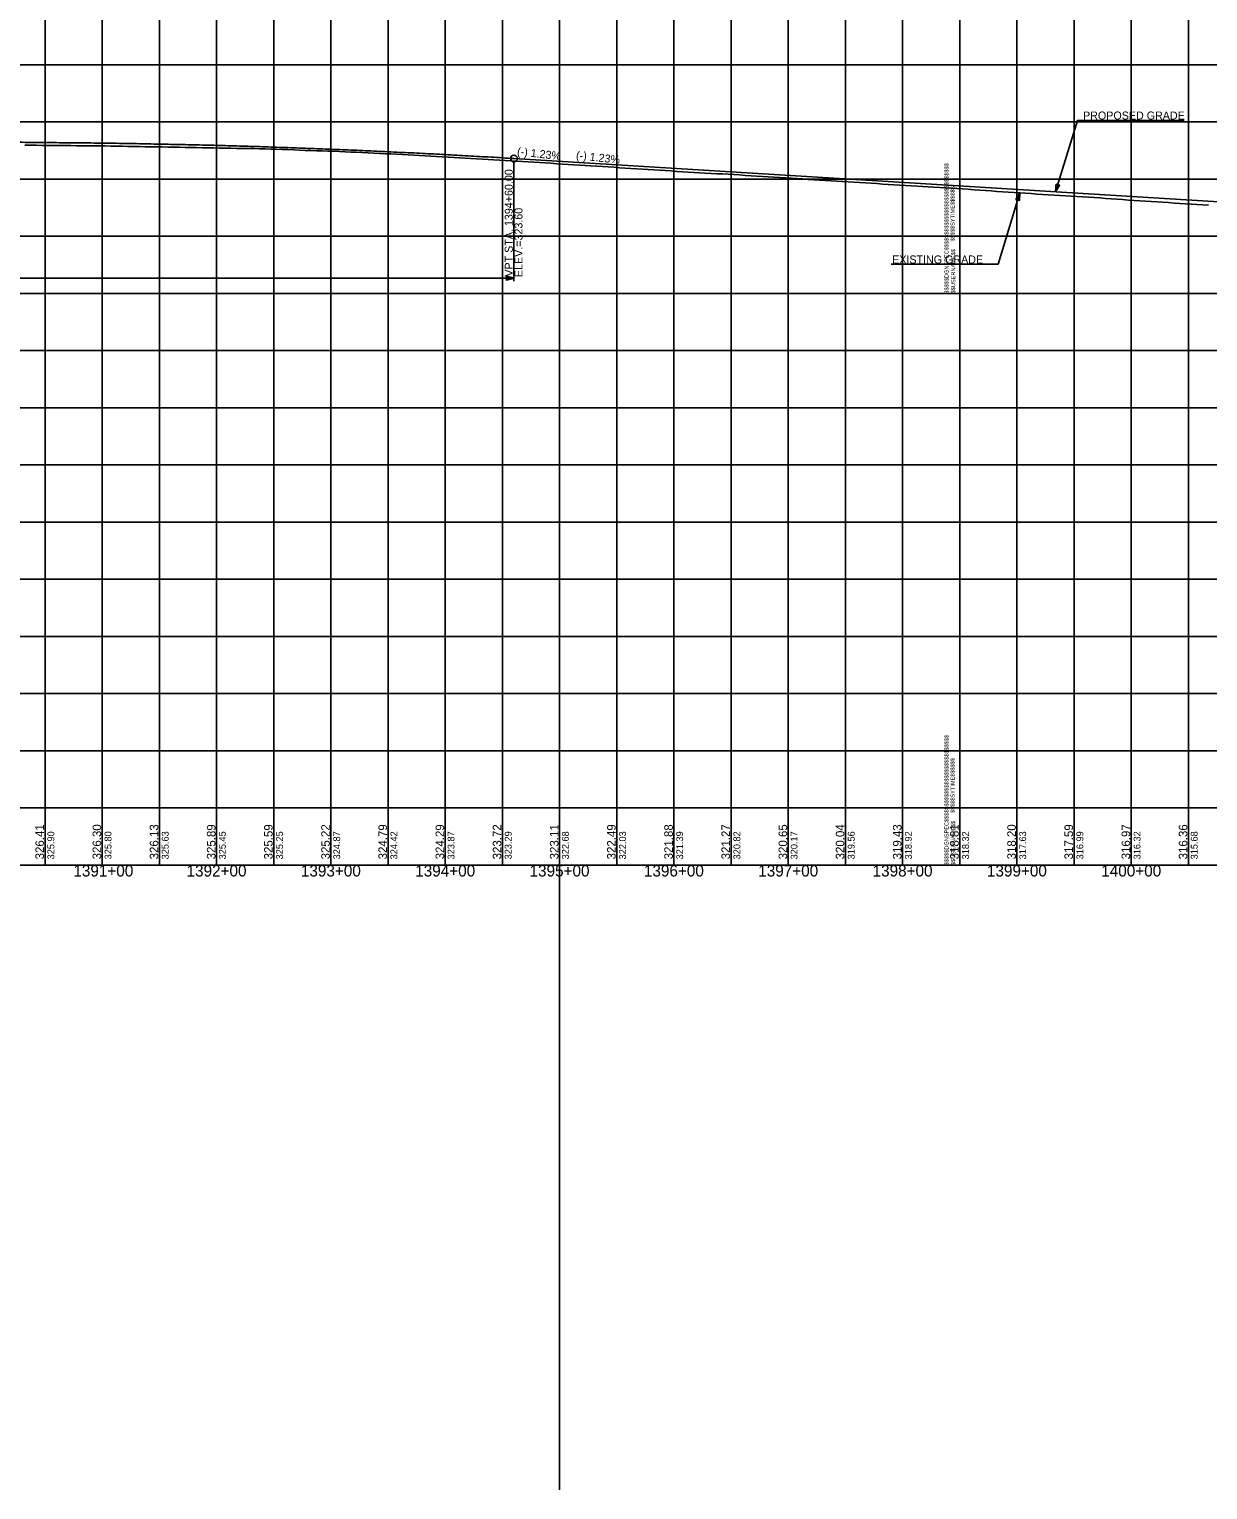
# Model space of a CAD drawing. Extents: x -90830 to 2015517, y -20856 to 836331.
# Drawn here: x 27960 to 28990, y -11344 to -10066 of the extents above; entities that cross this region are included whole.
import ezdxf

# ---------------------------------------------------------------- set-up
doc = ezdxf.new("R2010")
doc.units = 0
for name, color, linetype in [('Level 1', 7, 'Continuous'), ('RD_DDB_GradeTX', 7, 'Continuous'), ('RD_DDB_Profile_Elev', 7, 'Continuous'), ('RD_DDB_Profile_EX', 7, 'Continuous'), ('RD_DDB_Profile_PR', 7, 'Continuous'), ('RD_DDB_StaTX', 7, 'Continuous'), ('RD_DDB_StripGrade', 7, 'Continuous'), ('RD_DDB_VCLbl', 7, 'Continuous'), ('RD_GPK_Profile_Cell', 7, 'Continuous'), ('RD_PD_Final_TX', 7, 'Continuous'), ('RD_TX_Drainage', 7, 'Continuous')]:
    doc.layers.add(name, color=color, linetype=linetype)

msp = doc.modelspace()

# ---------------------------------------------------------------- linework, layer by layer
at = {"layer": 'Level 1'}
for p, q in [((28423.5, -3180.8), (28423.5, -11343.5)), ((27973.5, -9797.1), (27973.5, -10297.1)), ((28023.5, -9797.1), (28023.5, -10297.1)), ((28073.5, -9797.1), (28073.5, -10297.1)), ((28123.5, -9797.1), (28123.5, -10297.1)), ((28173.5, -9797.1), (28173.5, -10297.1)), ((28223.5, -9797.1), (28223.5, -10297.1)), ((28273.5, -9797.1), (28273.5, -10297.1)), ((28323.5, -9797.1), (28323.5, -10297.1)), ((28373.5, -9797.1), (28373.5, -10297.1)), ((28423.5, -9797.1), (28423.5, -10297.1)), ((28473.5, -9797.1), (28473.5, -10297.1)), ((28523.5, -9797.1), (28523.5, -10297.1)), ((28573.5, -9797.1), (28573.5, -10297.1)), ((28623.5, -9797.1), (28623.5, -10297.1)), ((28673.5, -9797.1), (28673.5, -10297.1)), ((28723.5, -9797.1), (28723.5, -10297.1)), ((28773.5, -9797.1), (28773.5, -10297.1)), ((28773.5, -9797.1), (28773.5, -10297.1)), ((28773.5, -9797.1), (28773.5, -10297.1)), ((28823.5, -9797.1), (28823.5, -10297.1)), ((28873.5, -9797.1), (28873.5, -10297.1)), ((28923.5, -9797.1), (28923.5, -10297.1)), ((28973.5, -9797.1), (28973.5, -10297.1)), ((27173.5, -10097.1), (28773.5, -10097.1)), ((28773.5, -10097.1), (30373.5, -10097.1)), ((27173.5, -10147.1), (28773.5, -10147.1)), ((28773.5, -10147.1), (30373.5, -10147.1)), ((27173.5, -10197.1), (28773.5, -10197.1)), ((28773.5, -10197.1), (30373.5, -10197.1)), ((27173.5, -10247.1), (28773.5, -10247.1)), ((28773.5, -10247.1), (30373.5, -10247.1)), ((27173.5, -10297.1), (28773.5, -10297.1)), ((27173.5, -10297.1), (28773.5, -10297.1)), ((27973.5, -10297.1), (27973.5, -10797.1)), ((28023.5, -10297.1), (28023.5, -10797.1)), ((28073.5, -10297.1), (28073.5, -10797.1)), ((28123.5, -10297.1), (28123.5, -10797.1)), ((28173.5, -10297.1), (28173.5, -10797.1)), ((28223.5, -10297.1), (28223.5, -10797.1)), ((28273.5, -10297.1), (28273.5, -10797.1)), ((28323.5, -10297.1), (28323.5, -10797.1)), ((28373.5, -10297.1), (28373.5, -10797.1)), ((28423.5, -10297.1), (28423.5, -10797.1)), ((28473.5, -10297.1), (28473.5, -10797.1)), ((28523.5, -10297.1), (28523.5, -10797.1)), ((28573.5, -10297.1), (28573.5, -10797.1)), ((28623.5, -10297.1), (28623.5, -10797.1)), ((28673.5, -10297.1), (28673.5, -10797.1)), ((28723.5, -10297.1), (28723.5, -10797.1)), ((28773.5, -10297.1), (30373.5, -10297.1)), ((28773.5, -10297.1), (28773.5, -10797.1)), ((28773.5, -10297.1), (28773.5, -10797.1)), ((28773.5, -10297.1), (30373.5, -10297.1)), ((28773.5, -10297.1), (28773.5, -10797.1)), ((28823.5, -10297.1), (28823.5, -10797.1)), ((28873.5, -10297.1), (28873.5, -10797.1)), ((28923.5, -10297.1), (28923.5, -10797.1)), ((28973.5, -10297.1), (28973.5, -10797.1)), ((27173.5, -10347.1), (28773.5, -10347.1)), ((28773.5, -10347.1), (30373.5, -10347.1)), ((27173.5, -10397.1), (28773.5, -10397.1)), ((28773.5, -10397.1), (30373.5, -10397.1)), ((27173.5, -10447.1), (28773.5, -10447.1)), ((28773.5, -10447.1), (30373.5, -10447.1)), ((27173.5, -10497.1), (28773.5, -10497.1)), ((28773.5, -10497.1), (30373.5, -10497.1)), ((27173.5, -10547.1), (28773.5, -10547.1)), ((28773.5, -10547.1), (30373.5, -10547.1)), ((27173.5, -10597.1), (28773.5, -10597.1)), ((28773.5, -10597.1), (30373.5, -10597.1)), ((27173.5, -10647.1), (28773.5, -10647.1)), ((28773.5, -10647.1), (30373.5, -10647.1)), ((27173.5, -10697.1), (28773.5, -10697.1)), ((28773.5, -10697.1), (30373.5, -10697.1)), ((27173.5, -10747.1), (28773.5, -10747.1)), ((28773.5, -10747.1), (30373.5, -10747.1)), ((27173.5, -10797.1), (28773.5, -10797.1)), ((28773.5, -10797.1), (30373.5, -10797.1))]:
    msp.add_line(p, q, dxfattribs=at)
at = {"layer": 'RD_DDB_Profile_EX'}
for points in [[(27955.9, -10167.4), (27960.9, -10167.5), (27965.9, -10167.5), (27970.9, -10167.6), (27975.9, -10167.6), (27980.9, -10167.7), (27985.9, -10167.8), (27990.9, -10167.8), (27995.9, -10167.8), (28000.9, -10167.9), (28005.9, -10167.9), (28010.9, -10168), (28015.9, -10168), (28020.9, -10168.1), (28025.9, -10168.1), (28030.9, -10168.2), (28035.9, -10168.3), (28040.9, -10168.4), (28045.9, -10168.5)], [(28045.9, -10168.5), (28050.9, -10168.6), (28055.9, -10168.7), (28060.9, -10168.8), (28065.9, -10168.9), (28070.9, -10168.9), (28075.9, -10169), (28080.9, -10169.1), (28085.9, -10169.2), (28090.9, -10169.3), (28095.9, -10169.4), (28100.9, -10169.5), (28105.9, -10169.5), (28110.9, -10169.6), (28115.9, -10169.7), (28120.9, -10169.8), (28125.9, -10169.9), (28130.9, -10170), (28135.9, -10170.1), (28140.9, -10170.2), (28145.9, -10170.3), (28150.9, -10170.3), (28155.9, -10170.4), (28160.9, -10170.5), (28165.9, -10170.6), (28170.9, -10170.8), (28175.9, -10171), (28180.9, -10171.1), (28185.9, -10171.3), (28190.9, -10171.5), (28195.9, -10171.8), (28200.9, -10172), (28205.9, -10172.2), (28210.9, -10172.4), (28215.9, -10172.5), (28220.9, -10172.7), (28225.9, -10172.8), (28230.9, -10173), (28235.9, -10173.2), (28240.9, -10173.4), (28245.9, -10173.6), (28250.9, -10173.9), (28255.9, -10174.1), (28260.9, -10174.4), (28265.9, -10174.6), (28270.9, -10174.9), (28275.9, -10175.1), (28280.9, -10175.4), (28285.9, -10175.6), (28290.9, -10175.9), (28295.9, -10176.1), (28300.9, -10176.4), (28305.9, -10176.7), (28310.9, -10177), (28315.9, -10177.3), (28320.9, -10177.6), (28325.9, -10177.9), (28330.9, -10178.2), (28335.9, -10178.5), (28340.9, -10178.8), (28345.9, -10179.1), (28350.9, -10179.3), (28355.9, -10179.6), (28360.9, -10179.9), (28365.9, -10180.2), (28370.9, -10180.5), (28375.9, -10180.8), (28380.9, -10181.1), (28385.9, -10181.4), (28390.9, -10181.8), (28395.9, -10182.1), (28400.9, -10182.4), (28405.9, -10182.7), (28410.9, -10183), (28415.9, -10183.3), (28420.9, -10183.6), (28425.9, -10183.9), (28430.9, -10184.2), (28435.9, -10184.5), (28440.9, -10184.8), (28445.9, -10185.2), (28450.9, -10185.5), (28455.9, -10185.8), (28460.9, -10186.1), (28465.9, -10186.5), (28470.9, -10186.8), (28475.9, -10187.2), (28480.9, -10187.5), (28485.9, -10187.8), (28490.9, -10188.1), (28495.9, -10188.4), (28500.9, -10188.8), (28505.9, -10189.1), (28510.9, -10189.4), (28515.9, -10189.7), (28520.9, -10190), (28525.9, -10190.3), (28530.9, -10190.6), (28535.9, -10191), (28540.9, -10191.3), (28545.9, -10191.6)], [(28545.9, -10191.6), (28550.9, -10191.8), (28555.9, -10192.1), (28560.9, -10192.4), (28565.9, -10192.6), (28570.9, -10192.9), (28575.9, -10193.2), (28580.9, -10193.5), (28585.9, -10193.8), (28590.9, -10194.1), (28595.9, -10194.4), (28600.9, -10194.7), (28605.9, -10195), (28610.9, -10195.4), (28615.9, -10195.8), (28620.9, -10196.1), (28625.9, -10196.4), (28630.9, -10196.7), (28635.9, -10197), (28640.9, -10197.3), (28645.9, -10197.6), (28650.9, -10197.9), (28655.9, -10198.3), (28660.9, -10198.6), (28665.9, -10198.9), (28670.9, -10199.2), (28675.9, -10199.5), (28680.9, -10199.8), (28685.9, -10200.1), (28690.9, -10200.4), (28695.9, -10200.7), (28700.9, -10201), (28705.9, -10201.4), (28710.9, -10201.7), (28715.9, -10202.1), (28720.9, -10202.4), (28725.9, -10202.7), (28730.9, -10202.9), (28735.9, -10203.2), (28740.9, -10203.5), (28745.9, -10203.8), (28750.9, -10204.1), (28755.9, -10204.4), (28760.9, -10204.7), (28765.9, -10205), (28770.9, -10205.4), (28775.9, -10205.7), (28780.9, -10206), (28785.9, -10206.4), (28790.9, -10206.8), (28795.9, -10207.1), (28800.9, -10207.5), (28805.9, -10207.8), (28810.9, -10208.2), (28815.9, -10208.5), (28820.9, -10208.8), (28825.9, -10209.1), (28830.9, -10209.5), (28835.9, -10209.8), (28840.9, -10210.2), (28845.9, -10210.5), (28850.9, -10210.8), (28855.9, -10211.1), (28860.9, -10211.4), (28865.9, -10211.7), (28870.9, -10212), (28875.9, -10212.3), (28880.9, -10212.6), (28885.9, -10212.9), (28890.9, -10213.3), (28895.9, -10213.6), (28900.9, -10214), (28905.9, -10214.4), (28910.9, -10214.7), (28915.9, -10215), (28920.9, -10215.4), (28925.9, -10215.7), (28930.9, -10216), (28935.9, -10216.4), (28940.9, -10216.7), (28945.9, -10217.1), (28950.9, -10217.4), (28955.9, -10217.7), (28960.9, -10218), (28965.9, -10218.3), (28970.9, -10218.6), (28975.9, -10218.9), (28980.9, -10219.2), (28985.9, -10219.5), (28990.9, -10219.8)]]:
    msp.add_lwpolyline(points, dxfattribs=at)
at = {"layer": 'RD_DDB_Profile_PR'}
msp.add_line((28383.5, -10179.1), (29048.5, -10219.9), dxfattribs=at)
msp.add_spline([(27383.5, -10183.8), (27403.5, -10182.4), (27423.5, -10181.1), (27443.5, -10179.8), (27463.5, -10178.6), (27483.5, -10177.4), (27503.5, -10176.3), (27523.5, -10175.2), (27543.5, -10174.2), (27563.5, -10173.2), (27583.5, -10172.3), (27603.5, -10171.4), (27623.5, -10170.6), (27643.5, -10169.9), (27663.5, -10169.2), (27683.5, -10168.5), (27703.5, -10167.9), (27723.5, -10167.4), (27743.5, -10166.9), (27763.5, -10166.5), (27783.5, -10166.1), (27803.5, -10165.8), (27823.5, -10165.5), (27843.5, -10165.3), (27863.5, -10165.1), (27883.5, -10165), (27903.5, -10164.9), (27923.5, -10164.9), (27943.5, -10164.9), (27963.5, -10165), (27983.5, -10165.2), (28003.5, -10165.4), (28023.5, -10165.6), (28043.5, -10165.9), (28063.5, -10166.3), (28083.5, -10166.7), (28103.5, -10167.1), (28123.5, -10167.6), (28143.5, -10168.2), (28163.5, -10168.8), (28183.5, -10169.5), (28203.5, -10170.2), (28223.5, -10171), (28243.5, -10171.8), (28263.5, -10172.7), (28283.5, -10173.7), (28303.5, -10174.6), (28323.5, -10175.7), (28343.5, -10176.8), (28363.5, -10177.9), (28383.5, -10179.1)], degree=3, dxfattribs=at)
at = {"layer": 'RD_DDB_VCLbl'}
for p, q in [((28383.5, -10286.3), (28383.5, -10182.1)), ((27383.5, -10283.8), (28383.5, -10283.8))]:
    msp.add_line(p, q, dxfattribs=at)
msp.add_circle((28383.5, -10179.1), 3, dxfattribs=at)
at = {"layer": 'RD_GPK_Profile_Cell'}
msp.add_line((4823.5, -10797.1), (75223.5, -10797.1), dxfattribs=at)
at = {"layer": 'RD_PD_Final_TX'}
for p, q in [((28857.3, -10208.2), (28857.7, -10201.5)), ((28859.2, -10202), (28857.3, -10208.2)), ((28857.3, -10208.2), (28860.7, -10202.4)), ((28857.7, -10201.5), (28860.7, -10202.4)), ((28825.9, -10209.1), (28822.5, -10214.9)), ((28825.6, -10215.8), (28822.5, -10214.9)), ((28824.1, -10215.3), (28825.9, -10209.1)), ((28825.9, -10209.1), (28825.6, -10215.8))]:
    msp.add_line(p, q, dxfattribs=at)
for points in [[(28969.7, -10145.8), (28876.4, -10145.8), (28857.3, -10208.2)], [(28859.1, -10202), (28857.4, -10207.8), (28859.1, -10202), (28857.4, -10207.5), (28859, -10202), (28857.4, -10207.3), (28859, -10202), (28857.4, -10207.1), (28858.9, -10201.9), (28857.4, -10206.7), (28858.8, -10201.9), (28857.5, -10206.3), (28858.7, -10201.9), (28857.5, -10206), (28858.7, -10201.9), (28857.5, -10205.7), (28858.6, -10201.9), (28857.5, -10205.4), (28858.5, -10201.8), (28857.5, -10205.2), (28858.4, -10201.8), (28857.5, -10204.8), (28858.4, -10201.8), (28857.6, -10204.4), (28858.3, -10201.7), (28857.6, -10204.1), (28858.2, -10201.7), (28857.6, -10203.6), (28858.1, -10201.7), (28857.6, -10203.3), (28858.1, -10201.7), (28857.6, -10202.9), (28858, -10201.7), (28857.7, -10202.7), (28857.9, -10201.6), (28857.7, -10202.3), (28857.8, -10201.6), (28857.7, -10201.9), (28857.8, -10201.6)], [(28857.5, -10207.8), (28859.2, -10202.1), (28857.6, -10207.6), (28859.3, -10202.1), (28857.7, -10207.4), (28859.4, -10202.1), (28857.8, -10207.2), (28859.4, -10202.1), (28857.9, -10207), (28859.5, -10202.1), (28858, -10206.9), (28859.5, -10202.1), (28858.2, -10206.6), (28859.6, -10202.1), (28858.3, -10206.4), (28859.7, -10202.2), (28858.5, -10206.1), (28859.7, -10202.2), (28858.6, -10205.9), (28859.8, -10202.2), (28858.8, -10205.6), (28859.9, -10202.2), (28858.9, -10205.4), (28859.9, -10202.3), (28859.1, -10205), (28860, -10202.3), (28859.3, -10204.8), (28860, -10202.2), (28859.5, -10204.5), (28860.1, -10202.3), (28859.6, -10204.2), (28860.2, -10202.3), (28859.7, -10204), (28860.2, -10202.4), (28859.9, -10203.7), (28860.3, -10202.4), (28860.1, -10203.4), (28860.4, -10202.4), (28860.2, -10203.2), (28860.5, -10202.4), (28860.3, -10203.1), (28860.6, -10202.5), (28860.7, -10202.5), (28860.5, -10202.5)], [(28713.5, -10271.5), (28806.9, -10271.5), (28825.9, -10209.1)], [(28825.8, -10209.5), (28824, -10215.3), (28825.7, -10209.7), (28824, -10215.2), (28825.6, -10209.9), (28823.9, -10215.2), (28825.5, -10210.1), (28823.9, -10215.2), (28825.3, -10210.3), (28823.8, -10215.2), (28825.2, -10210.5), (28823.7, -10215.2), (28825.1, -10210.7), (28823.7, -10215.2), (28824.9, -10211), (28823.6, -10215.1), (28824.8, -10211.2), (28823.5, -10215.2), (28824.7, -10211.4), (28823.5, -10215.1), (28824.5, -10211.7), (28823.4, -10215.1), (28824.3, -10211.9), (28823.4, -10215), (28824.1, -10212.3), (28823.3, -10215.1), (28824, -10212.5), (28823.2, -10215.1), (28823.8, -10212.8), (28823.2, -10215), (28823.7, -10213.1), (28823.1, -10215), (28823.5, -10213.3), (28823, -10214.9), (28823.3, -10213.6), (28823, -10214.9), (28823.2, -10213.9), (28822.9, -10214.9), (28823.1, -10214.1), (28822.8, -10214.9), (28822.9, -10214.2), (28822.7, -10214.8), (28822.6, -10214.8), (28822.7, -10214.8)], [(28824.1, -10215.3), (28825.9, -10209.5), (28824.2, -10215.3), (28825.9, -10209.8), (28824.2, -10215.3), (28825.9, -10210), (28824.3, -10215.3), (28825.9, -10210.2), (28824.4, -10215.4), (28825.8, -10210.6), (28824.5, -10215.4), (28825.8, -10211), (28824.5, -10215.4), (28825.8, -10211.3), (28824.6, -10215.4), (28825.8, -10211.6), (28824.7, -10215.4), (28825.7, -10211.9), (28824.7, -10215.5), (28825.7, -10212.1), (28824.8, -10215.5), (28825.7, -10212.5), (28824.9, -10215.5), (28825.7, -10212.9), (28825, -10215.6), (28825.7, -10213.2), (28825, -10215.6), (28825.7, -10213.7), (28825.1, -10215.6), (28825.6, -10214), (28825.2, -10215.7), (28825.6, -10214.4), (28825.3, -10215.6), (28825.6, -10214.7), (28825.3, -10215.7), (28825.6, -10215), (28825.4, -10215.7), (28825.6, -10215.4), (28825.5, -10215.7)]]:
    msp.add_lwpolyline(points, dxfattribs=at)
at = {"layer": 'RD_TX_Drainage'}
msp.add_lwpolyline([(28376.9, -10282.1), (28383.5, -10283.8), (28376.9, -10285.4)], close=True, dxfattribs=at)

# ---------------------------------------------------------------- texts
at = {"layer": 'Level 1'}
for s, p in [('$$$$$DGNSPEC$$$$$$$$$$$$$$$$$$$$$$$$$$$$', (28763.6, -10297.2)), ('$$$$$SYTIME$$$$$$', (28768.9, -10251.6)), ('$$USERNAME$$', (28769.5, -10297)), ('$$$$$DGNSPEC$$$$$$$$$$$$$$$$$$$$$$$$$$$$', (28763.6, -10797.2)), ('$$$$$SYTIME$$$$$$', (28768.9, -10751.6)), ('$$USERNAME$$', (28769.5, -10797))]:
    msp.add_text(s, height=3.544, rotation=90, dxfattribs=at).set_placement(p)
at = {"layer": 'RD_DDB_GradeTX'}
for p in [(28386, -10176.2), (28437.6, -10179.5)]:
    msp.add_text('(-) 1.23%', height=7, rotation=353.5197, dxfattribs=at).set_placement(p)
at = {"layer": 'RD_DDB_Profile_Elev'}
for s, p in [('326.41', (27972.5, -10792.1)), ('326.30', (28022.5, -10792.1)), ('326.13', (28072.5, -10792.1)), ('325.89', (28122.5, -10792.1)), ('325.59', (28172.5, -10792.1)), ('325.22', (28222.5, -10792.1)), ('324.79', (28272.5, -10792.1)), ('324.29', (28322.5, -10792.1)), ('323.72', (28372.5, -10792.1)), ('323.11', (28422.5, -10792.1)), ('322.49', (28472.5, -10792.1)), ('321.88', (28522.5, -10792.1)), ('321.27', (28572.5, -10792.1)), ('320.65', (28622.5, -10792.1)), ('320.04', (28672.5, -10792.1)), ('319.43', (28722.5, -10792.1)), ('318.81', (28772.5, -10792.1)), ('318.20', (28822.5, -10792.1)), ('317.59', (28872.5, -10792.1)), ('316.97', (28922.5, -10792.1)), ('316.36', (28972.5, -10792.1))]:
    msp.add_text(s, height=7.5, rotation=90, dxfattribs=at).set_placement(p)
at = {"layer": 'RD_DDB_StaTX'}
for s, p in [('1391+00', (27998.2, -10807.1)), ('1392+00', (28097.2, -10807.1)), ('1393+00', (28197.2, -10807.1)), ('1394+00', (28297.2, -10807.1)), ('1395+00', (28397.2, -10807.1)), ('1396+00', (28497.2, -10807.1)), ('1397+00', (28597.2, -10807.1)), ('1398+00', (28697.2, -10807.1)), ('1399+00', (28797.2, -10807.1)), ('1400+00', (28897.2, -10807.1))]:
    msp.add_text(s, height=10, dxfattribs=at).set_placement(p)
at = {"layer": 'RD_DDB_StripGrade'}
for s, height, p in [('VPT STA. 1394+60.00 ', 7, (28382.5, -10282.4)), ('ELEV.=323.60', 7, (28391, -10282.8)), ('325.90', 6, (27981.5, -10792.1)), ('325.80', 6, (28031.5, -10792.1)), ('325.63', 6, (28081.5, -10792.1)), ('325.45', 6, (28131.5, -10792.1)), ('325.25', 6, (28181.5, -10792.1)), ('324.87', 6, (28231.5, -10792.1)), ('324.42', 6, (28281.5, -10792.1)), ('323.87', 6, (28331.5, -10792.1)), ('323.29', 6, (28381.5, -10792.1)), ('322.68', 6, (28431.5, -10792.1)), ('322.03', 6, (28481.5, -10792.1)), ('321.39', 6, (28531.5, -10792.1)), ('320.82', 6, (28581.5, -10792.1)), ('320.17', 6, (28631.5, -10792.1)), ('319.56', 6, (28681.5, -10792.1)), ('318.92', 6, (28731.5, -10792.1)), ('318.32', 6, (28781.5, -10792.1)), ('317.63', 6, (28831.5, -10792.1)), ('316.99', 6, (28881.5, -10792.1)), ('316.32', 6, (28931.5, -10792.1)), ('315.68', 6, (28981.5, -10792.1))]:
    msp.add_text(s, height=height, rotation=90, dxfattribs=at).set_placement(p)
at = {"layer": 'RD_PD_Final_TX'}
for s, p in [('PROPOSED GRADE', (28881.3, -10145)), ('EXISTING GRADE', (28714.3, -10270.9))]:
    msp.add_text(s, height=7, dxfattribs=at).set_placement(p)

doc.saveas('drawing.dxf')
